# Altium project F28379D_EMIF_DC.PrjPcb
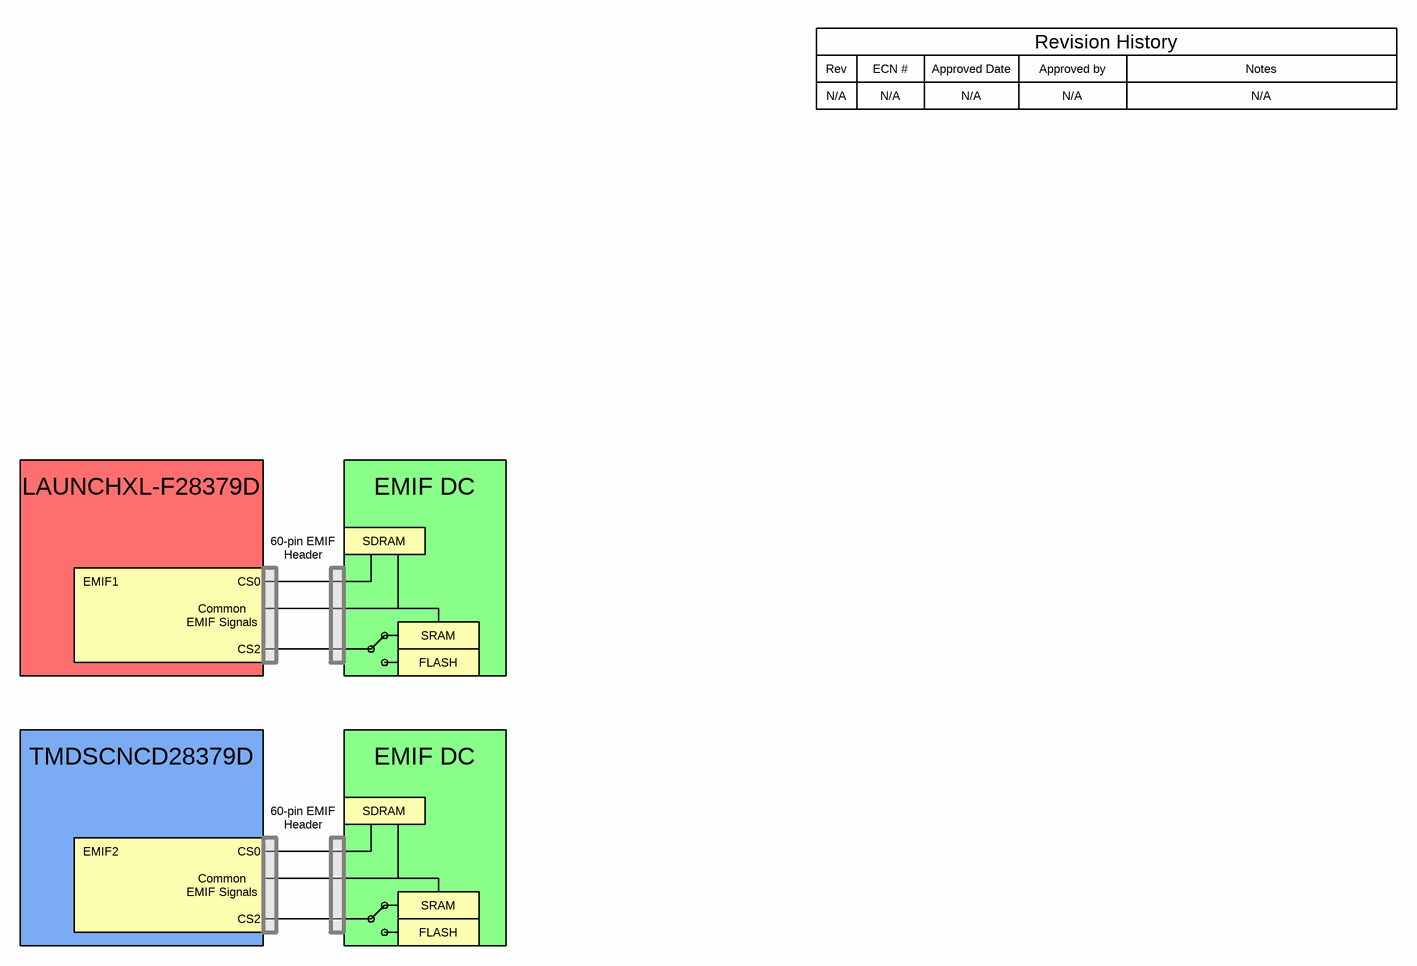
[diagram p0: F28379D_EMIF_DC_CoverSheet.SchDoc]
CopyrightYear: 2017; PCB_Layout: Tommy Lee; PCB_Rev: E1; PRJ_Customer: Public Release; PRJ_Engineer: Tommy Lee; PRJ_Number: F28379D_EMIF_DC; PRJ_Title: F28379D_EMIF_DC; SCH_Rev: E1; TechSupport: http://www.ti.com/support; TID: N/A
3 sheets, 52 parts. Net scope: global (net labels, ports and power ports of the same name join across sheets).
Board file: F28379D_EMIF_DC_PCB.PcbDoc
Sheets:
  F28379D_EMIF_DC_CoverSheet.SchDoc
  F28379D_EMIF_DC_Memory.SchDoc
  F28379D_EMIF_DC_Hardware.SchDoc

## Sheet F28379D_EMIF_DC_CoverSheet.SchDoc
size 431 x 279 mm; Date: Not shown in title block; ApprovedBy: Not shown in title block; CheckedBy: Not shown in title block; Author: Not shown in title block; CompanyName: Not shown in title block; Engineer: Not shown in title block; Organization: Not shown in title block; Address1: Not shown in title block; Address2: Not shown in title block; Address3: Not shown in title block; Address4: Not shown in title block; DocumentNumber: 1; Revision: Use project parameter SCH_Rev; SheetNumber: 1; SheetTotal: 3; PageSetup: Record=PageOptions¦CenterHorizontal=True¦CenterVertical=True¦PrintScale=1.00¦XCorrection=1.00¦YCorrection=1.00¦PrintKind=0¦BorderSize=5000000¦LeftOffset=0¦BottomOffset=0¦Orientation=2¦PaperLength=1000¦PaperWidth=1000¦Scale=100¦PaperSource=15¦PrintQuality=600¦MediaType=1¦DitherType=10¦PaperKind=Letter¦PrintScaleMode=1

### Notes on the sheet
- Rev
- N/A
- ECN #
- Approved Date
- Approved by
- Revision History
- Notes
- LAUNCHXL-F28379D
- EMIF DC
- 60-pin EMIF
- Header
- SDRAM
- EMIF1
- EMIF Signals
- Common
- CS0
- SRAM
- CS2
- FLASH
- TMDSCNCD28379D
- EMIF2

## Sheet F28379D_EMIF_DC_Memory.SchDoc
size 431 x 279 mm; Date: Not shown in title block; ApprovedBy: Not shown in title block; CheckedBy: Not shown in title block; Author: Not shown in title block; CompanyName: Not shown in title block; Engineer: Not shown in title block; Organization: Not shown in title block; Address1: Not shown in title block; Address2: Not shown in title block; Address3: Not shown in title block; Address4: Not shown in title block; DocumentNumber: 1; Revision: Use project parameter SCH_Rev; SheetNumber: 2; SheetTotal: 3; PageSetup: Record=PageOptions¦CenterHorizontal=True¦CenterVertical=True¦PrintScale=1.00¦XCorrection=1.00¦YCorrection=1.00¦PrintKind=0¦BorderSize=5000000¦LeftOffset=0¦BottomOffset=0¦Orientation=2¦PaperLength=1000¦PaperWidth=1000¦Scale=100¦PaperSource=15¦PrintQuality=600¦MediaType=1¦DitherType=10¦PaperKind=Letter¦PrintScaleMode=1
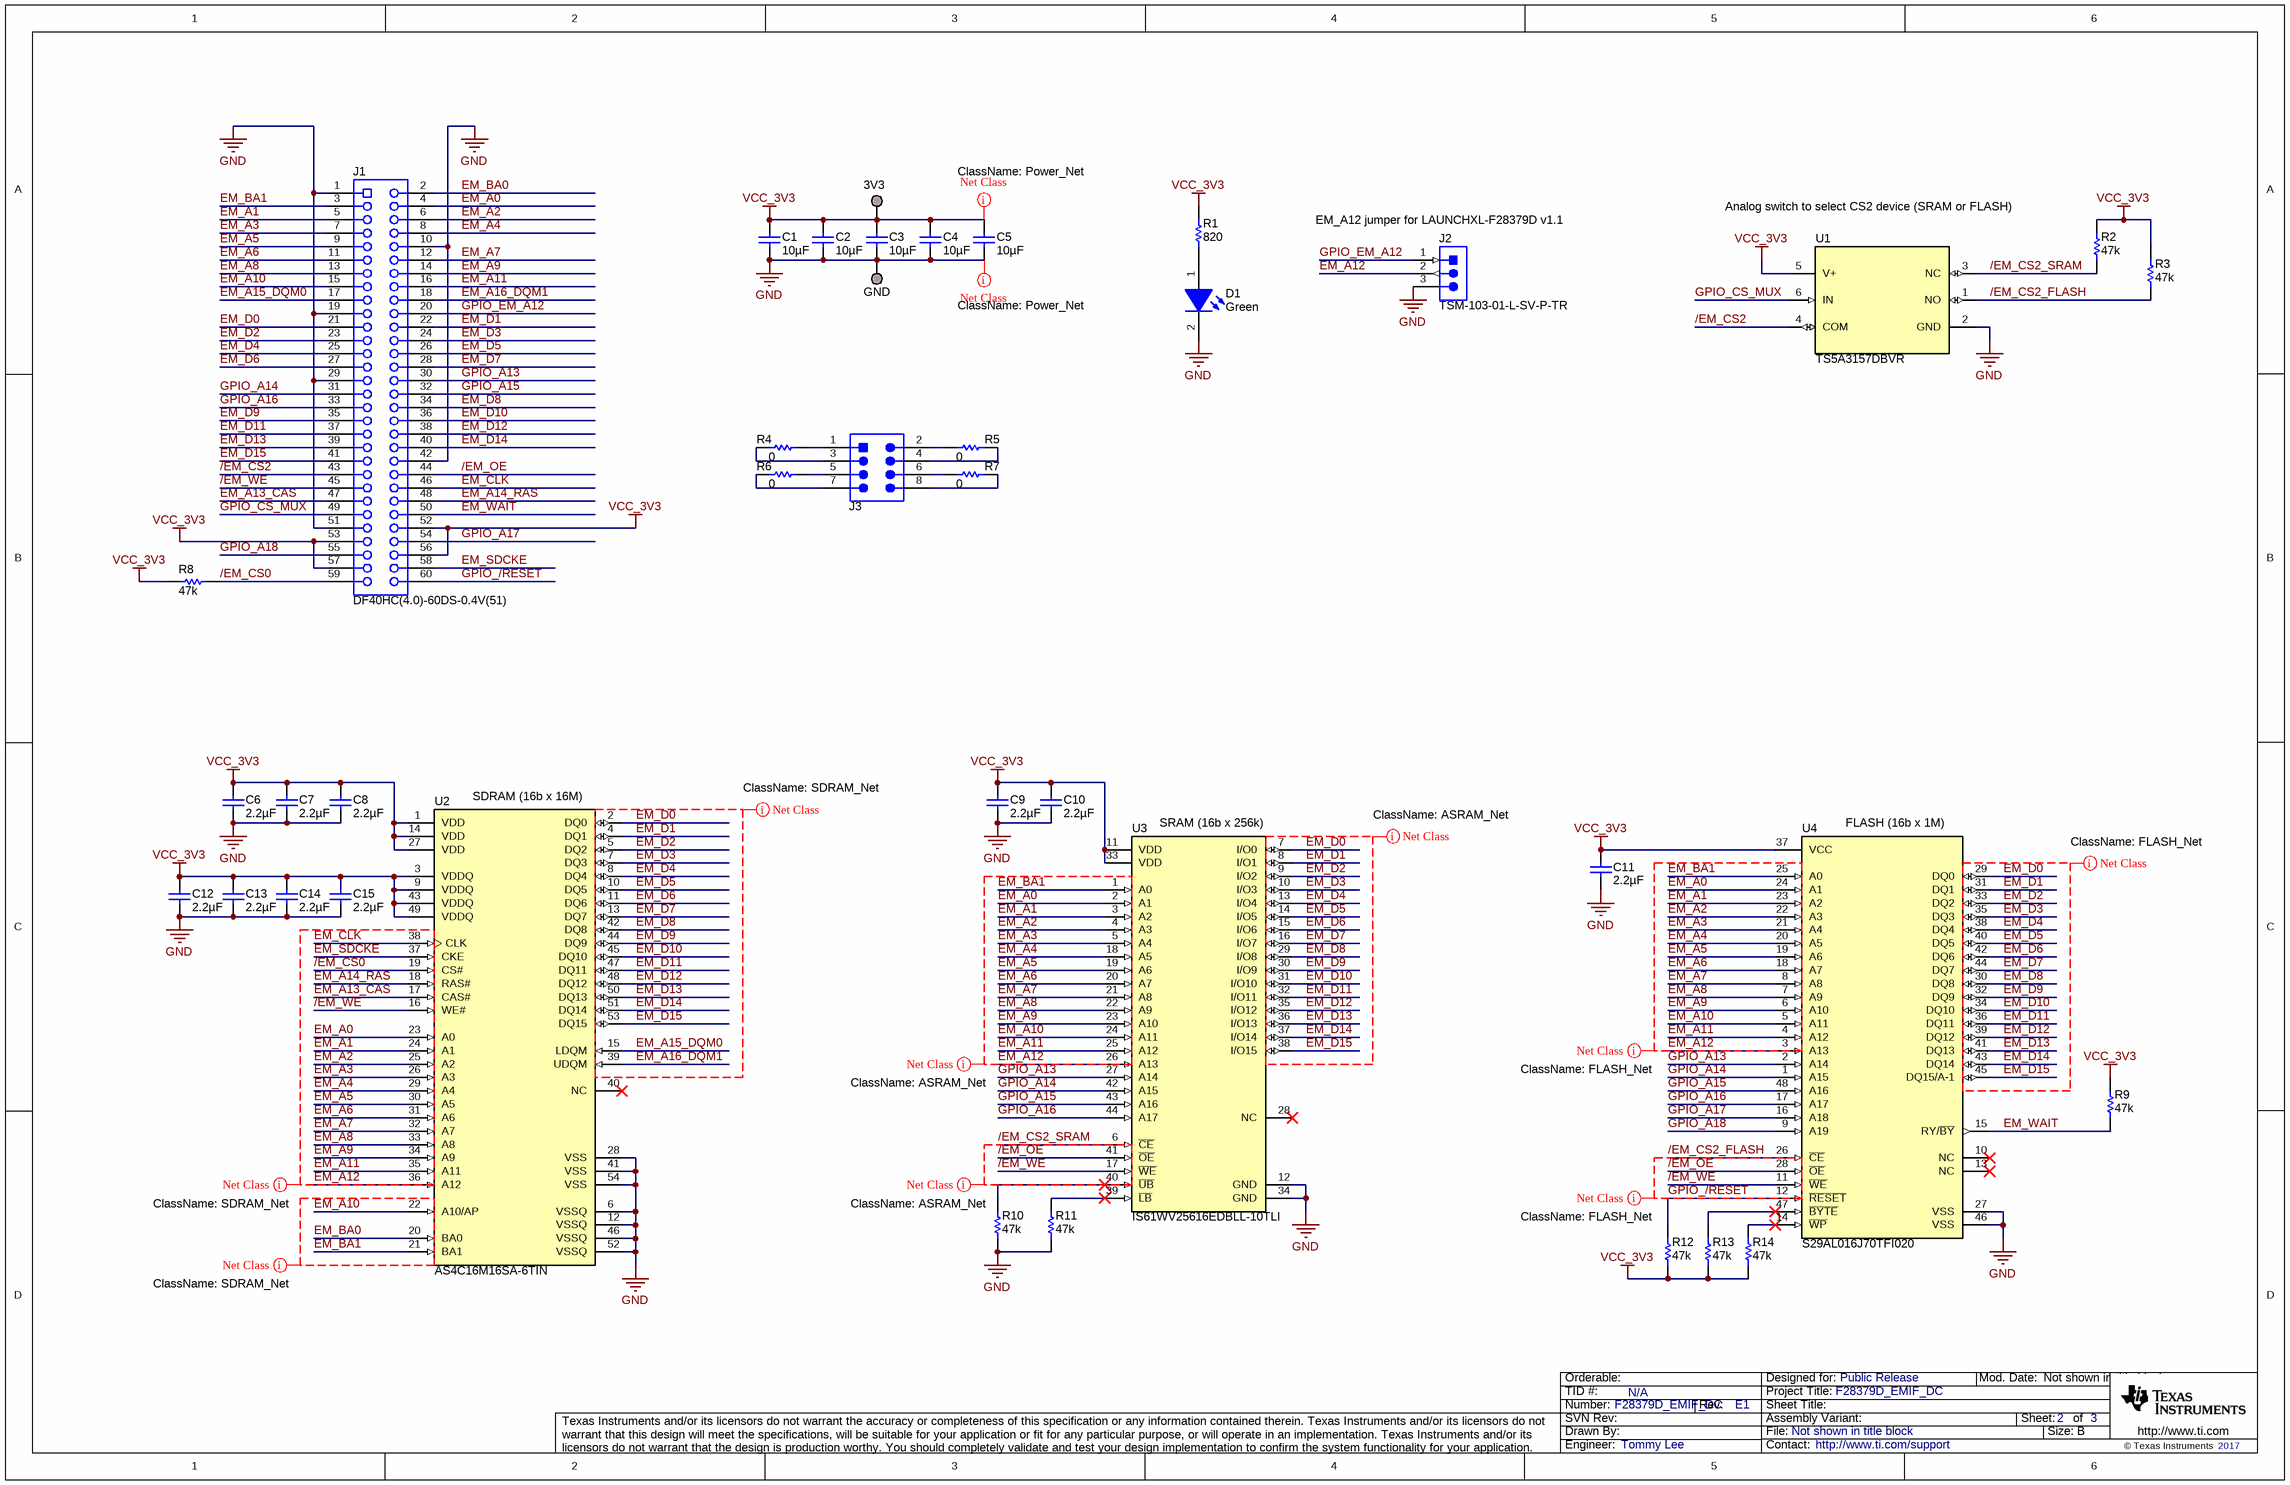
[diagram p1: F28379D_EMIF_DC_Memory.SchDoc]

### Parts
3V3  TESTPOINT  [TP_50MIL-25MILHOLE]  (value not drawn)  (no BOM)
C1  ValueDisplayed: 10µF  [0603L]  (hidden comment: C1608X5R1A106M080AC)
C2  ValueDisplayed: 10µF  [0603L]  (hidden comment: C1608X5R1A106M080AC)
C3  ValueDisplayed: 10µF  [0603L]  (hidden comment: C1608X5R1A106M080AC)
C4  ValueDisplayed: 10µF  [0603L]  (hidden comment: C1608X5R1A106M080AC)
C5  ValueDisplayed: 10µF  [0603L]  (hidden comment: C1608X5R1A106M080AC)
C6  ValueDisplayed: 2.2µF  [0603L]  (hidden comment: GRM188R71A225KE15D)
C7  ValueDisplayed: 2.2µF  [0603L]  (hidden comment: GRM188R71A225KE15D)
C8  ValueDisplayed: 2.2µF  [0603L]  (hidden comment: GRM188R71A225KE15D)
C9  ValueDisplayed: 2.2µF  [0603L]  (hidden comment: GRM188R71A225KE15D)
C10  ValueDisplayed: 2.2µF  [0603L]  (hidden comment: GRM188R71A225KE15D)
C11  ValueDisplayed: 2.2µF  [0603L]  (hidden comment: GRM188R71A225KE15D)
C12  ValueDisplayed: 2.2µF  [0603L]  (hidden comment: GRM188R71A225KE15D)
C13  ValueDisplayed: 2.2µF  [0603L]  (hidden comment: GRM188R71A225KE15D)
C14  ValueDisplayed: 2.2µF  [0603L]  (hidden comment: GRM188R71A225KE15D)
C15  ValueDisplayed: 2.2µF  [0603L]  (hidden comment: GRM188R71A225KE15D)
D1  value Green  [APHHS1005_Green]  (hidden comment: APHHS1005CGCK)
GND  TESTPOINT  [TP_50MIL-25MILHOLE]  (value not drawn)  (no BOM)
J1  DF40HC(4.0)-60DS-0.4V(51)  [Hirose_DF40HC-4_0-60DS-0_4V_Reverse]
J2  TSM-103-01-L-SV-P-TR  [Samtec_TSM-103-01-x-SV-P]
J3  TSM-104-01-L-DV  [Samtec_TSM-104-01-x-DV]  (value not drawn)
R1  ValueDisplayed: 820  [0603]  (hidden comment: CRCW0603820RJNEA)
R2  ValueDisplayed: 47k  [0603L]  (hidden comment: RC0603JR-0747KL)
R3  ValueDisplayed: 47k  [0603L]  (hidden comment: RC0603JR-0747KL)
R4  ValueDisplayed: 0  [0603L]  (hidden comment: CRCW06030000Z0EA)
R5  ValueDisplayed: 0  [0603L]  (hidden comment: CRCW06030000Z0EA)
R6  ValueDisplayed: 0  [0603L]  (hidden comment: CRCW06030000Z0EA)
R7  ValueDisplayed: 0  [0603L]  (hidden comment: CRCW06030000Z0EA)
R8  ValueDisplayed: 47k  [0603L]  (hidden comment: RC0603JR-0747KL)
R9  ValueDisplayed: 47k  [0603L]  (hidden comment: RC0603JR-0747KL)
R10  ValueDisplayed: 47k  [0603L]  (hidden comment: RC0603JR-0747KL)
R11  ValueDisplayed: 47k  [0603L]  (hidden comment: RC0603JR-0747KL)
R12  ValueDisplayed: 47k  [0603L]  (hidden comment: RC0603JR-0747KL)
R13  ValueDisplayed: 47k  [0603L]  (hidden comment: RC0603JR-0747KL)
R14  ValueDisplayed: 47k  [0603L]  (hidden comment: RC0603JR-0747KL)
U1  TS5A3157DBVR  [DBV0006A_N]
U2  AS4C16M16SA-6TIN  [TSOP-2_54]
U3  IS61WV25616EDBLL-10TLI  [TSOP-2_44]
U4  S29AL016J70TFI020  [TSOP-48]

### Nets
GND: C1.2 C2.2 C3.2 C4.2 C5.2 C6.2 C7.2 C8.2 C9.2 C10.2 C11.2 C12.2 C13.2 C14.2 C15.2 D1.2(K) GND.1 J1.1 J1.10 J1.19 J1.29 J1.42 J1.51 J2.3 R10.1 R11.1 U1.2(GND) U2.6(VSSQ) U2.12(VSSQ) U2.28(VSS) U2.41(VSS) U2.46(VSSQ) U2.52(VSSQ) U2.54(VSS) U3.12(GND) U3.34(GND) U4.27(VSS) U4.46(VSS)
VCC_3V3: 3V3.1 C1.1 C2.1 C3.1 C4.1 C5.1 C6.1 C7.1 C8.1 C9.1 C10.1 C11.1 C12.1 C13.1 C14.1 C15.1 J1.52 J1.53 J1.56 J1.57 R1.2 R2.2 R3.2 R8.2 R9.2 R12.1 R13.1 R14.1 U1.5(V+) U2.1(VDD) U2.3(VDDQ) U2.9(VDDQ) U2.14(VDD) U2.27(VDD) U2.43(VDDQ) U2.49(VDDQ) U3.11(VDD) U3.33(VDD) U4.37(VCC)
/EM_CS0: J1.59 R8.1 U2.19(CS#)
/EM_CS2: J1.43 U1.4(COM)
/EM_CS2_FLASH: R3.1 U1.1(NO) U4.26(~{CE})
/EM_CS2_SRAM: R2.1 U1.3(NC) U3.6(~{CE})
/EM_OE: J1.44 U3.41(~{OE}) U4.28(~{OE})
/EM_WE: J1.45 U2.16(WE#) U3.17(~{WE}) U4.11(~{WE})
EM_A0: J1.4 U2.23(A0) U3.2(A1) U4.24(A1)
EM_A1: J1.5 U2.24(A1) U3.3(A2) U4.23(A2)
EM_A2: J1.6 U2.25(A2) U3.4(A3) U4.22(A3)
EM_A3: J1.7 U2.26(A3) U3.5(A4) U4.21(A4)
EM_A4: J1.8 U2.29(A4) U3.18(A5) U4.20(A5)
EM_A5: J1.9 U2.30(A5) U3.19(A6) U4.19(A6)
EM_A6: J1.11 U2.31(A6) U3.20(A7) U4.18(A7)
EM_A7: J1.12 U2.32(A7) U3.21(A8) U4.8(A8)
EM_A8: J1.13 U2.33(A8) U3.22(A9) U4.7(A9)
EM_A9: J1.14 U2.34(A9) U3.23(A10) U4.6(A10)
EM_A10: J1.15 U2.22(A10/AP) U3.24(A11) U4.5(A11)
EM_A11: J1.16 U2.35(A11) U3.25(A12) U4.4(A12)
EM_A12: J2.2 U2.36(A12) U3.26(A13) U4.3(A13)
EM_A13_CAS: J1.47 U2.17(CAS#)
EM_A14_RAS: J1.48 U2.18(RAS#)
EM_A15_DQM0: J1.17 U2.15(LDQM)
EM_A16_DQM1: J1.18 U2.39(UDQM)
EM_BA0: J1.2 U2.20(BA0)
EM_BA1: J1.3 U2.21(BA1) U3.1(A0) U4.25(A0)
EM_CLK: J1.46 U2.38(CLK)
EM_D0: J1.21 U2.2(DQ0) U3.7(I/O0) U4.29(DQ0)
EM_D1: J1.22 U2.4(DQ1) U3.8(I/O1) U4.31(DQ1)
EM_D2: J1.23 U2.5(DQ2) U3.9(I/O2) U4.33(DQ2)
EM_D3: J1.24 U2.7(DQ3) U3.10(I/O3) U4.35(DQ3)
EM_D4: J1.25 U2.8(DQ4) U3.13(I/O4) U4.38(DQ4)
EM_D5: J1.26 U2.10(DQ5) U3.14(I/O5) U4.40(DQ5)
EM_D6: J1.27 U2.11(DQ6) U3.15(I/O6) U4.42(DQ6)
EM_D7: J1.28 U2.13(DQ7) U3.16(I/O7) U4.44(DQ7)
EM_D8: J1.34 U2.42(DQ8) U3.29(I/O8) U4.30(DQ8)
EM_D9: J1.35 U2.44(DQ9) U3.30(I/O9) U4.32(DQ9)
EM_D10: J1.36 U2.45(DQ10) U3.31(I/O10) U4.34(DQ10)
EM_D11: J1.37 U2.47(DQ11) U3.32(I/O11) U4.36(DQ11)
EM_D12: J1.38 U2.48(DQ12) U3.35(I/O12) U4.39(DQ12)
EM_D13: J1.39 U2.50(DQ13) U3.36(I/O13) U4.41(DQ13)
EM_D14: J1.40 U2.51(DQ14) U3.37(I/O14) U4.43(DQ14)
EM_D15: J1.41 U2.53(DQ15) U3.38(I/O15) U4.45(DQ15/A-1)
EM_SDCKE: J1.58 U2.37(CKE)
EM_WAIT: J1.50 R9.1 U4.15(RY/~{BY})
GPIO_/RESET: J1.60 R12.2 U4.12(~{RESET})
GPIO_A13: J1.30 U3.27(A14) U4.2(A14)
GPIO_A14: J1.31 U3.42(A15) U4.1(A15)
GPIO_A15: J1.32 U3.43(A16) U4.48(A16)
GPIO_A16: J1.33 U3.44(A17) U4.17(A17)
GPIO_A17: J1.54 U4.16(A18)
GPIO_A18: J1.55 U4.9(A19)
GPIO_CS_MUX: J1.49 U1.6(IN)
GPIO_EM_A12: J1.20 J2.1
NetD1_1: D1.1(A) R1.1
NetJ3_1: J3.1 R4.2
NetJ3_2: J3.2 R5.1
NetJ3_3: J3.3 R4.1
NetJ3_4: J3.4 R5.2
NetJ3_5: J3.5 R6.2
NetJ3_6: J3.6 R7.1
NetJ3_7: J3.7 R6.1
NetJ3_8: J3.8 R7.2
NetR10_2: R10.2 U3.40(~{UB})
NetR11_2: R11.2 U3.39(~{LB})
NetR13_2: R13.2 U4.47(~{BYTE})
NetR14_2: R14.2 U4.14(~{WP})

Not connected (* = marked no-connect by the designer): U2 40(NC)*; U3 28(NC)*; U4 10(NC)* 13(NC)*

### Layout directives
net class Power_Net: GND, VCC_3V3
net class SDRAM_Net: /EM_CS0, /EM_WE, EM_A0, EM_A1, EM_A2, EM_A3, EM_A4, EM_A5, EM_A6, EM_A7, EM_A8, EM_A9, EM_A10, EM_A11, EM_A12, EM_A13_CAS, EM_A14_RAS, EM_A15_DQM0, EM_A16_DQM1, EM_BA0, EM_BA1, EM_CLK, EM_D0, EM_D1, EM_D2, EM_D3, EM_D4, EM_D5, EM_D6, EM_D7, EM_D8, EM_D9, EM_D10, EM_D11, EM_D12, EM_D13, EM_D14, EM_D15, EM_SDCKE
net class ASRAM_Net: /EM_CS2_SRAM, /EM_OE, /EM_WE, EM_A0, EM_A1, EM_A2, EM_A3, EM_A4, EM_A5, EM_A6, EM_A7, EM_A8, EM_A9, EM_A10, EM_A11, EM_A12, EM_BA1, EM_D0, EM_D1, EM_D2, EM_D3, EM_D4, EM_D5, EM_D6, EM_D7, EM_D8, EM_D9, EM_D10, EM_D11, EM_D12, EM_D13, EM_D14, EM_D15
net class FLASH_Net: /EM_CS2_FLASH, /EM_OE, /EM_WE, EM_A0, EM_A1, EM_A2, EM_A3, EM_A4, EM_A5, EM_A6, EM_A7, EM_A8, EM_A9, EM_A10, EM_A11, EM_A12, EM_BA1, EM_D0, EM_D1, EM_D2, EM_D3, EM_D4, EM_D5, EM_D6, EM_D7, EM_D8, EM_D9, EM_D10, EM_D11, EM_D12, EM_D13, EM_D14, EM_D15, GPIO_/RESET

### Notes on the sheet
- (near J2) EM_A12 jumper for LAUNCHXL-F28379D v1.1
- Analog switch to select CS2 device (SRAM or FLASH)
- (near U2) SDRAM (16b x 16M)
- (near U3) SRAM (16b x 256k)
- (near U4) FLASH (16b x 1M)

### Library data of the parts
3V3 GND = TESTPOINT: TEST POINT.  No entry in BOM.
C1-C5 = C1608X5R1A106M080AC: CAP, CERM, 10 µF, 10 V, +/- 20%, X5R, 0603; Manufacturer: TDK; Polarized: N; CompType: Capacitor; Value: 10uF; U/M: EA; Cap_F: 0.00001; Tolerance_%: 20; ESR_ohm: 0.0078; Value1: 0.0078 ohm; VDC_V: 10; Value2: 10V; IRMS_A: 1.85; TaMin_C: -55; TaMax_C: 85; Cap_Case: 0603; SizeArea_mm2: 1.28; SizeAreaWB_mm2: 4.68; SizeX_mm: 1.6; SizeY_mm: 0.8; SizeZ_mm: 1; AEC Category: Q200
C6-C15 = GRM188R71A225KE15D: CAP, CERM, 2.2 µF, 10 V, +/- 10%, X7R, 0603; Manufacturer: MuRata; Polarized: N; CompType: Capacitor; Value: 2.2uF; U/M: EA; Cap_F: 0.0000022; Tolerance_%: 10; ESR_ohm: 0.009; Value1: 0.009 ohm; Value2: 10V; TaMin_C: -55; TaMax_C: 125; Cap_Case: 0603; SizeArea_mm2: 1.28; SizeAreaWB_mm2: 4.68; SizeX_mm: 1.6; SizeY_mm: 0.8; SizeZ_mm: 1; AEC Category: Q200
D1 = APHHS1005CGCK: LED, Green, SMD; Manufacturer: Kingbright; Vf_V: 2.1; Value2: 2.1V; Io_A: 0.02; Vr_V: 5; Ir_A: 1e-005; Tjmax_C: 85; Power_TotalModule: 0.075; Value1: 0.075W; Angle: 120; SizeAreaWB_mm2: 3; SizeArea_mm2: 0.5; SizeX_mm: 1; SizeZ_mm: 0.6; U/M: EA
J1 = DF40HC(4.0)-60DS-0.4V(51): Receptacle, 0.4mm, 30x2, Gold, SMT; Manufacturer: Hirose Electric Co. Ltd.; SymbolCreator: Altium; Pitch_mm: 0.4; Gender: Female; Row_Count: 2; Current_A: 0.3; Voltage_V: 30; Cert_UL: Y
J2 = TSM-103-01-L-SV-P-TR: Header, 2.54mm, 3x1, Gold, SMT; Manufacturer: Samtec; SymbolCreator: a0799628; Pitch_mm: 2.54; Gender: Male; Shrouded: N; Row_Count: 1; Current_A: 5.4; Voltage_V: 475; Cert_CSA: Y
J3 = TSM-104-01-L-DV: Header, 2.54mm, 4x2, Gold, SMT; Manufacturer: Samtec; SymbolCreator: a0411947; Pitch_mm: 2.54; Gender: Male; Shrouded: N; Row_Count: 2; Current_A: 4.9; Voltage_V: 475; Cert_CSA: Y
R1 = CRCW0603820RJNEA: RES, 820, 5%, 0.1 W, 0603; Manufacturer: Vishay-Dale; CompType: Resistor; Value: 820; Value_Code: 820R; Tolerance_%: 5; Power_W: 0.1; Value2: 0.1W; VDC_V: 75; TempCo: 200 ppm/C; SizeArea_mm2: 1.28; SizeX_mm: 1.6; SizeY_mm: 0.8; SizeZ_mm: 1; EIA_Code: E24; U/M: EA; AEC Category: Q200
R2 R3 R8-R14 = RC0603JR-0747KL: RES, 47 k, 5%, 0.1 W, 0603; Manufacturer: Yageo America; CompType: Resistor; Value: 47k; Res_ohm: 47000; Value_Code: 47k0; Tolerance_%: 5; Power_W: 0.1; Value2: 0.1W; VDC_V: 50; TempCo: 100 ppm/C; SizeArea_mm2: 1.28; SizeX_mm: 1.6; SizeY_mm: 0.8; SizeZ_mm: 1; EIA_Code: E24; U/M: EA; AEC Category: Q200
R4-R7 = CRCW06030000Z0EA: RES, 0, 5%, 0.1 W, 0603; Manufacturer: Vishay-Dale; CompType: Resistor; Value: 0; Value_Code: 0000; Tolerance_%: 5; Power_W: 0.1; Value2: 0.1W; VDC_V: 75; TempCo: 200 ppm/C; SizeArea_mm2: 1.28; SizeX_mm: 1.6; SizeY_mm: 0.8; SizeZ_mm: 1; EIA_Code: E24; U/M: EA; AEC Category: Q200; Green_Lifecycle: Active; Green_REACh: Passed
U1 = TS5A3159DBVR: 1-Ohm SPDT Analog Switch, DBV0006A (SOT-23-6); Alternate PartNumber: TS5A3159DBVT; Manufacturer: Texas Instruments; SymbolCreator: a0799628; SizeArea_mm2: 8.12; SizeAreaWB_mm2: 14.82; SizeX_mm: 2.8; SizeY_mm: 2.9; SizeZ_mm: 1.45; CompType: IC; U/M: EA
U2 = AS4C16M16SA-6TIN: 256M - (16Mx16bit) Synchronous DRAM (SDRAM); Manufacturer: Alliance Memory; SymbolCreator: Altium; SizeAreaWB_mm2: 333.2672; SizeArea_mm2: 261.3072; SizeX_mm: 11.76; SizeY_mm: 22.22; SizeZ_mm: 1.2
U3 = IS61WV25616EDBLL-10TLI: 256K x 16 High Speed Asynchronous CMOS Static RAM with ECC; Manufacturer: Integrated Silicon Solution Inc.; SymbolCreator: Altium; SizeAreaWB_mm2: 280.8416; SizeArea_mm2: 216.5016; SizeX_mm: 11.76; SizeY_mm: 18.41; SizeZ_mm: 1.2
U4 = S29AL016J70TFI020: 16 Mbit (2 M x 8-Bit/1 M x 16-Bit), 3 V Boot Sector Flash; Manufacturer: Cypress Semiconductor; SymbolCreator: Altium; SizeAreaWB_mm2: 308; SizeArea_mm2: 240; SizeX_mm: 20; SizeY_mm: 12; SizeZ_mm: 1.2

## Sheet F28379D_EMIF_DC_Hardware.SchDoc
size 431 x 279 mm; Date: Not shown in title block; ApprovedBy: Not shown in title block; CheckedBy: Not shown in title block; Author: Not shown in title block; CompanyName: Not shown in title block; Engineer: Not shown in title block; Organization: Not shown in title block; Address1: Not shown in title block; Address2: Not shown in title block; Address3: Not shown in title block; Address4: Not shown in title block; DocumentNumber: 1; Revision: Use project parameter SCH_Rev; SheetNumber: 3; SheetTotal: 3; PageSetup: Record=PageOptions¦CenterHorizontal=True¦CenterVertical=True¦PrintScale=1.00¦XCorrection=1.00¦YCorrection=1.00¦PrintKind=0¦BorderSize=5000000¦LeftOffset=0¦BottomOffset=0¦Orientation=2¦PaperLength=1000¦PaperWidth=1000¦Scale=100¦PaperSource=15¦PrintQuality=600¦MediaType=1¦DitherType=10¦PaperKind=Letter¦PrintScaleMode=1
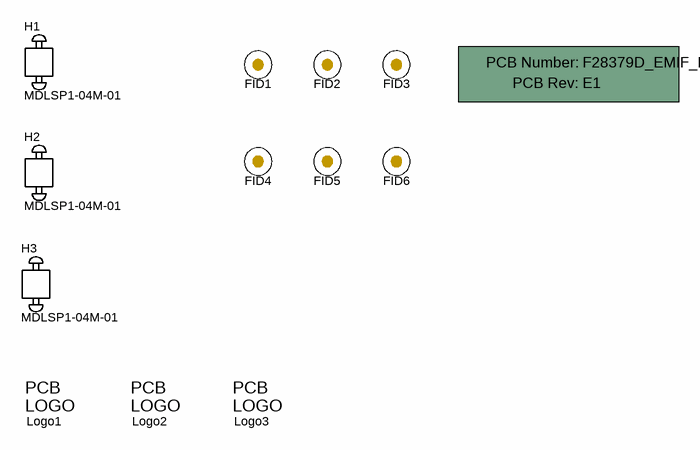
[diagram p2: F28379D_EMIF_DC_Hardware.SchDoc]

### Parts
!PCB1  Printed Circuit Board  (value not drawn)  (mechanical)
FID1  Fiducial  [Fiducial6.4-20]  (value not drawn)
FID2  Fiducial  [Fiducial6.4-20]  (value not drawn)
FID3  Fiducial  [Fiducial6.4-20]  (value not drawn)
FID4  Fiducial  [Fiducial6.4-20]  (value not drawn)
FID5  Fiducial  [Fiducial6.4-20]  (value not drawn)
FID6  Fiducial  [Fiducial6.4-20]  (value not drawn)
H1  MDLSP1-04M-01  [Essentra_MDLSP1-04M-01]
H2  MDLSP1-04M-01  [Essentra_MDLSP1-04M-01]
H3  MDLSP1-04M-01  [Essentra_MDLSP1-04M-01]
Logo1  Texas Instruments  [TI_Symbol_Overlay_Small]  (value not drawn)  (no BOM)
Logo2  FCC disclaimer  [FCC_disclaimer]  (value not drawn)  (no BOM)
Logo3  Pb-Free Symbol  [Pb-Free_Overlay_Small]  (value not drawn)  (no BOM)

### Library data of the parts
!PCB1 = PCB: Manufacturer: Any; PartNumber: F28379D_EMIF_DC; SymbolCreator: a0412235
FID1-FID6 = Fiducial: Fiducial mark.  There is nothing to buy or mount.; SymbolCreator: codlsc
H1-H3 = MDLSP1-04M-01: Snap Lock, Nylon, 0.157" (4.00mm); Manufacturer: Essentra Components; SymbolCreator: Altium
Logo1 = TI_Logo: Texas Instrument Corporate Signature; SymbolCreator: a0412235
Logo2 = FCC_disclaimer: SymbolCreator: a0412235
Logo3 = Pb-Free: SymbolCreator: a0412235

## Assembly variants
001: not fitted J3 R4 R5 R6 R7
